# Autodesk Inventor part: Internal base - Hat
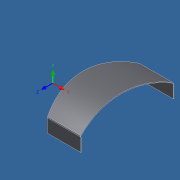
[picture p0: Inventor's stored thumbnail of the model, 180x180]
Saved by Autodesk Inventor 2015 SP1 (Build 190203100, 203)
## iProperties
Category: Mechanical Engineering Drawing and Design - CADD
Manager: Fábio Ricardo de Oliveira Souza
Company: SENAI - Serviço Nacional de Aprendizagem Industrial
Created: 2011-06
Part Number: Internal base - Hat
Material: Steel
Description: Stainless Steel (Din- X6CrNiTi18-10)
Document SubType Name: Sheet Metal
Designer: Guilherme Augusto Franco de Souza
Engineer: George Geraldo de Oliveia Silva
Authority: Fábio Ricardo de Oliveira Soza
Density: 7.85 g/cm^3
Sheet Metal Rule: Default_mm
Sheet Metal Width: 534,130 mm
Sheet Metal Length: 193,672 mm
Sheet Metal Area: 103445,746 mm^2
Flat Pattern Width: 53.413 cm
Flat Pattern Length: 19.3672 cm
Flat Pattern Area: 1034.46 cm^2
Appearance: Machined 02
Subject: WorldSkill 2011 - London, England
Author: Guilherme Augusto Franco de Souza
Revision Number: 00
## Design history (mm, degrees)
sketch "Sketch1"
  geometry: L1 (-175, 0)-(-175, 60); L2 (-175, 60)-(-110, 125); L3 (-110, 125)-(110, 125); L4 (110, 125)-(175, 60); L5 (175, 60)-(175, 0); L6 (175, 0)-(323.5, 0); L7 (-175, 0)-(-323.5, 0); 2 further points
  constraints: 14 end point, 5 equal length, 2 horizontal alignment, 2 perpendicular, 1 midpoint, 1 vertical, 1 vertical alignment
  dimensions: "d0" = 125 distance from line of L3 L5.end; "d1" = 60 distance of L4.end L5.end; "d2" = 220 distance of L2.end L3.end; "d3" = 148.5 distance of L5.end L6.end; "d4" = 647 distance of L7.end L6.end
extrude_surface "ExtrusionSrf1" sketch "Sketch1" dims "d5" = 597, "d6" = 0
sketch "Sketch2"
  geometry: L1 (60, 298.5)-(125, 298.5) reference; L2 (60, 298.5)-(177.438, 230.697); L3 (125, -298.5)-(60, -298.5) reference; L4 (60, -298.5)-(177.438, -230.697); L5 (60, -298.5)-(195.606, -298.5); 1 further point
  constraints: 6 end point, 2 equal length, 1 horizontal
  dimensions: "d7" = 30 deg angle of L1 L2; "d8" = 30 deg angle of L5 L4
split "Split1"
split "Split2"
delete_face "Delete Face1"
sketch "Sketch3"
  geometry: L1 (0, 200)-(60.502, 200); L2 (0, -200)-(60.502, -200); L3 (0, -280)-(0, 280) reference; A1 r 444.82 centre (-336.82, 0) between (60.502, -200) and (60.502, 200); 1 further point
  constraints: 4 end point, 2 parallel, 2 point on circle, 1 centre point, 1 horizontal, 1 horizontal alignment, 1 vertical alignment
  dimensions: "d10" = 200 distance from line of point (0, 0) L1; "d11" = 400 distance between parallel lines of L2 L1 (= 2 x d10); "d12" = 108 distance edge to line of A1 L3; "d13" = 444.82 radius of A1
extrude_surface "ExtrusionSrf2" sketch "Sketch3" dims "d94" = 323.5, "d95" = 0
feature "OffsetSrf1" dims "d106" = 2, "d121" = 2
split "Split4"
delete_face "Delete Face3"
sketch "Sketch11"
  geometry: L1 (323.5, 108)-(323.5, 60.502) reference; L2 (323.5, 56)-(266.968, 166); 1 further point
  constraints: 2 end point, 1 point on line
  dimensions: "d96" = 27.2 deg angle of L1 L2; "d108" = 56 vertical distance of point (0, 0) L2.start
split "Split5"
delete_face "Delete Face4"
fillet "Fillet2" dims "d97" = 2 (= Thickness)
thicken "Thicken2" dims "d98" = 2 (= Thickness)
feature "Corner Round1" dims "d107" = 0.5
extrude_surface "ExtrusionSrf3" dims "d109" = 489.5, "d110" = 0
split "Split6"
body "Solid2"
body "Srf1"
body "Srf2"
body "Srf3"
body "Srf4"
feature "Definition1"
other parameters: "Thickness" = 2 (derived), "BendRadius" = 2 (= Thickness), "BendReliefWidth" = 2 (= Thickness), "BendReliefDepth" = 1 (= 0.5 x Thickness), "CornerReliefSize" = 8 (= 4 x Thickness), "SeamGap" = 0.01, "MinimumRemnant" = 4 (= 2 x Thickness), "TransitionRadius" = 2 (= BendRadius), "JacobiRadiusSize" = 2 (= BendRadius), "GapSize" = 2 (= Thickness), "d99" = 0, "d100" = 0, "d101" = 0, "d102" = 0, "d103" = 0, "d104" = 0, "d122" = 0.5, "d123" = 2, "d124" = 0, "BendRadius" = 2, "BendReliefDepth" = 1, "BendReliefWidth" = 2, "CornerReliefSize" = 8, "GapSize" = 2, "JacobiRadiusSize" = 2, "MinimumRemnant" = 4, "Thickness" = 2, "TransitionRadius" = 2
